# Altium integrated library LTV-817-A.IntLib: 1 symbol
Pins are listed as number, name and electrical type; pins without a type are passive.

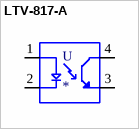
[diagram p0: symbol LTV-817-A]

## LTV-817-A
designator U
Optoisolator Transistor Output 5000Vrms 1 Channel 4-DIP; MP: LTV-817-A; MF: Lite-On Inc.
footprint DIP762W50P254L510H500Q4
pins: 1 A, 2 C, 3 ET, 4 CT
